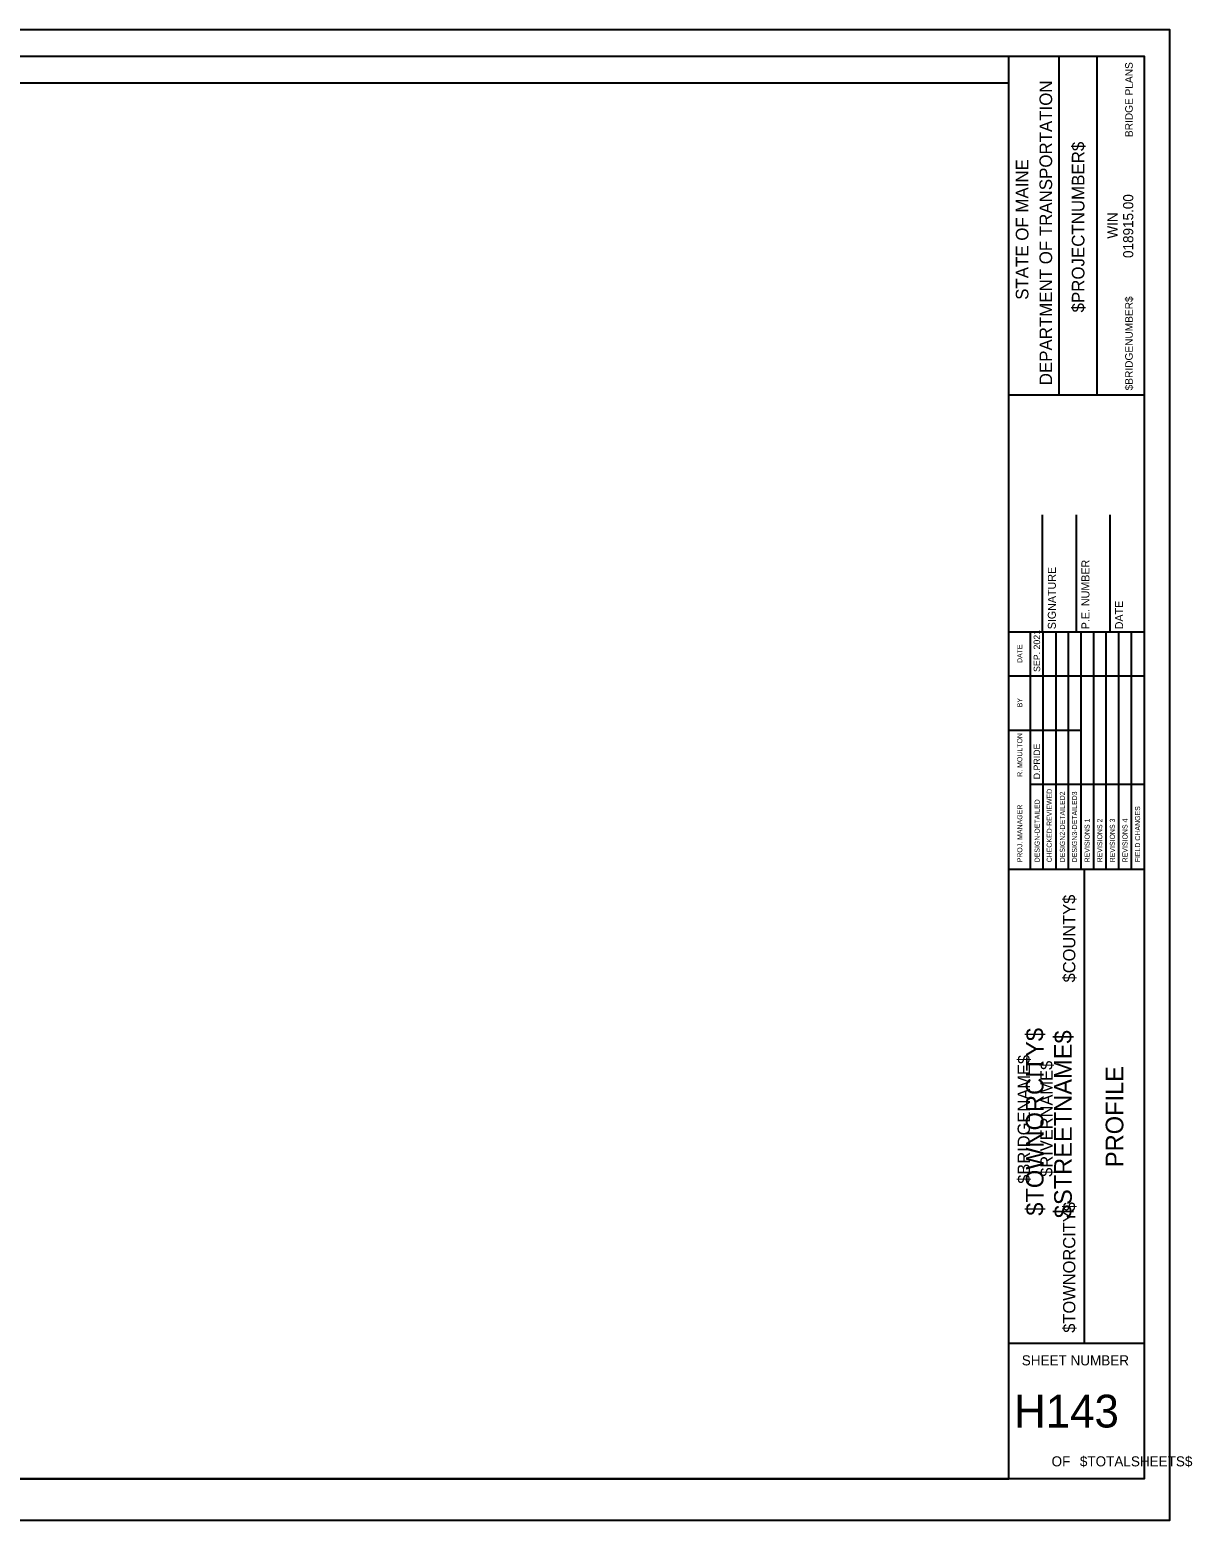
# Model space of a CAD drawing. Extents: x 9960 to 10818, y 9985 to 10535.
# Drawn here: x 10389 to 10818, y 9985 to 10535 of the extents above; entities that cross this region are included whole.
import ezdxf

# ---------------------------------------------------------------- set-up
doc = ezdxf.new("R2010")
doc.units = 0
for name, color, linetype in [('BORDER', 7, 'Continuous'), ('BRIDGE_TITLE', 7, 'Continuous'), ('CLIPS', 7, 'Continuous'), ('HIGHWAY_TITLE', 7, 'Continuous'), ('PLOT BOUNDARY', 7, 'Continuous')]:
    doc.layers.add(name, color=color, linetype=linetype)

msp = doc.modelspace()

# ---------------------------------------------------------------- linework, layer by layer
at = {"layer": 'BORDER'}
for p, q in [((10750, 10000), (10750, 10525)), ((10768.64, 10399.99), (10768.64, 10524.99)), ((10782.62, 10399.99), (10782.62, 10524.99)), ((10750, 10399.97), (10800, 10399.97)), ((10762.5, 10312.51), (10762.5, 10355.75)), ((10775, 10312.51), (10775, 10355.75)), ((10787.5, 10312.51), (10787.5, 10355.75)), ((10750, 10312.51), (10800, 10312.51)), ((10750, 10225.01), (10800, 10225.01)), ((10777.96, 10050.01), (10777.96, 10225.01)), ((10750, 10050.01), (10800, 10050.01))]:
    msp.add_line(p, q, dxfattribs=at)
msp.add_lwpolyline([(10000, 10525), (10800, 10525), (10800, 10000), (10000, 10000)], close=True, dxfattribs=at)
for points in [[(10758.07, 10296.26), (10758.07, 10312.51)], [(10762.74, 10225.03), (10762.74, 10312.51)], [(10767.4, 10312.51), (10767.4, 10225.03)], [(10772.05, 10225.03), (10772.05, 10312.51)], [(10776.71, 10225.03), (10776.71, 10312.51)], [(10781.37, 10225.03), (10781.37, 10312.51)], [(10786.03, 10225.03), (10786.03, 10312.51)], [(10790.69, 10225.03), (10790.69, 10312.51)], [(10795.35, 10225.03), (10795.35, 10312.51)], [(10758.08, 10225.03), (10758.08, 10308.98)], [(10750, 10296.26), (10800, 10296.26)], [(10750, 10276.26), (10758.08, 10276.26)], [(10758.07, 10276.26), (10776.71, 10276.26)], [(10758.07, 10256.26), (10800, 10256.26)]]:
    msp.add_lwpolyline(points, dxfattribs=at)
at = {"layer": 'CLIPS'}
msp.add_lwpolyline([(10000, 10000), (10750, 10000), (10750, 10515), (10000, 10515)], close=True, dxfattribs=at)
at = {"layer": 'PLOT BOUNDARY'}
msp.add_lwpolyline([(9959.53, 9984.7), (10809.53, 9984.7), (10809.53, 10534.7), (9959.53, 10534.7)], close=True, dxfattribs=at)

# ---------------------------------------------------------------- texts
at = {"layer": 'BORDER'}
for s, height, p in [('DEPARTMENT OF TRANSPORTATION', 4.6588, (10766.03, 10403.53)), ('$PROJECTNUMBER$', 4.6588, (10777.96, 10430.4)), ('STATE OF MAINE', 4.6588, (10757.28, 10435.06)), ('018915.00', 3.726, (10795.98, 10450.49)), ('WIN', 3.726, (10790.18, 10457.65)), ('SIGNATURE', 2.953, (10767.4, 10313.48)), ('P.E. NUMBER', 2.9528, (10779.8, 10313.48)), ('DATE', 2.953, (10792.21, 10313.48)), ('SEP. 2021', 2.423, (10761.61, 10297.74)), ('DATE', 1.857, (10755.02, 10301.04)), ('BY', 1.857, (10755.02, 10284.69)), ('R. MOULTON', 1.864, (10755.02, 10259.03)), ('D.PRIDE', 2.423, (10761.61, 10258.13)), ('CHECKED-REVIEWED', 1.8637, (10765.91, 10227.46)), ('DESIGN2-DETAILED2', 1.8637, (10770.75, 10227.46)), ('DESIGN3-DETAILED3', 1.8637, (10775.22, 10227.46)), ('PROJ. MANAGER', 1.8637, (10755.02, 10227.46)), ('DESIGN-DETAILED', 1.8637, (10761.43, 10227.46)), ('FIELD CHANGES', 1.8637, (10798.51, 10227.46)), ('REVISIONS 1', 1.8637, (10779.88, 10227.46)), ('REVISIONS 2', 1.8637, (10784.54, 10227.46)), ('REVISIONS 3', 1.8637, (10789.2, 10227.46)), ('REVISIONS 4', 1.8637, (10793.86, 10227.46)), ('PROFILE', 6.521, (10792.32, 10115))]:
    msp.add_text(s, height=height, rotation=90, dxfattribs=at).set_placement(p)
for s, height, p in [('SHEET NUMBER', 3.7264, (10754.83, 10041.83)), ('H143', 12.097, (10752, 10018.91)), ('OF', 3.726, (10765.83, 10004.56)), ('$TOTALSHEETS$', 3.7264, (10776.28, 10004.56))]:
    msp.add_text(s, height=height, dxfattribs=at).set_placement(p)
at = {"layer": 'BRIDGE_TITLE'}
for s, height, p in [('BRIDGE PLANS', 2.795, (10795.79, 10495.12)), ('$BRIDGENUMBER$', 2.795, (10795.79, 10401.65)), ('$COUNTY$', 4.536, (10774.6, 10183.17)), ('$BRIDGENAME$', 4.5358, (10757.83, 10108.86)), ('$RIVERNAME$', 4.5358, (10766.22, 10111.43)), ('$TOWNORCITY$', 4.5358, (10774.6, 10053.88))]:
    msp.add_text(s, height=height, rotation=90, dxfattribs=at).set_placement(p)
at = {"layer": 'HIGHWAY_TITLE'}
for s, p in [('$TOWNORCITY$', (10762.86, 10097.06)), ('$STREETNAME$', (10773.3, 10096.16))]:
    msp.add_text(s, height=6.5214, rotation=90, dxfattribs=at).set_placement(p)

doc.saveas('drawing.dxf')
